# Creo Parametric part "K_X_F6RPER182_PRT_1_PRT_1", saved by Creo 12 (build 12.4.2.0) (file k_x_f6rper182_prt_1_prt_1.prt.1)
Units: Custom; MM, KILOGRAM, SECS

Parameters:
  PTC_WM_ITERATION = "0"
  PTC_WM_VERSION = "-.0"
  PTC_WM_LIFECYCLE_STATE = "In Work"
  PTC_WM_LIFECYCLE = "MO_CADDocument"
  PTC_WM_CREATED_BY = "Maximilian Roepper (Z0017RMS: MO)"
  PTC_WM_CREATED_ON = "18-Sep-26 11:36:42 AM"
  PTC_WM_MODIFIED_BY = "Maximilian Roepper (Z0017RMS: MO)"
  PTC_WM_MODIFIED_ON = "18-Sep-26 11:36:46 AM"
  PDMLINKNUMBER = "PDM000071454792"
  PTC_WM_NAME = "k_x_f6rper182_prt_1_prt_1.prt"
  PTC_WM_NUMBER = "PDM000071454792"

Other parameters: WEIGHT, WEIGHT_FACTOR, WEIGHT_ADD, _MASS_TEMP, _DIFF_TEMP, MC_ERRORS, SUPPLIER

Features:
  1. coordinate system
  2. datum plane "PRT_YZ"
  3. datum plane "PRT_XY"
  4. datum plane "PRT_XZ"
  5. coordinate system
  6. datum axis
  7. datum axis
  8. datum axis
  9. coordinate system
  10. imported feature
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
Other named items: PRT, SIEMENS_MO, DRW_VIEW_ORG, PRT_X, PRT_Y, PRT_Z, CS0, ROUGH_GROB

Layers: 00_STD_CSYS-KSYS, 01_STD_PLANES-EBENEN, 02_STD_AXES-ACHSEN, 03_STD_CSYS-KSYS, 24_IMPORT_FEAT-IMPORT_KE

Surfaces: 16 tabulated cylinder, 4 plane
